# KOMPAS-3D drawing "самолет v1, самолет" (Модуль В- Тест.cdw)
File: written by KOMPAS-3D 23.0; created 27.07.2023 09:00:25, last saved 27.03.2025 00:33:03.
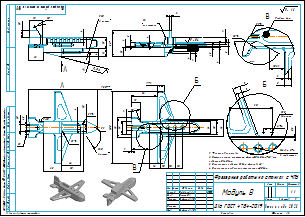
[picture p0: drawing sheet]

Sheet 1: A3, landscape

Document properties: Полное имя файла: C:\Users\safro\OneDrive\Рабочий стол\ИГ 2025\КЗ\Модуль В\Модуль В- Тест.cdw; Автор: Пользователь Windows

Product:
- Part/product: самолет v1  | designation самолет
    Масса: 0.217105
    source file: самолет.cdw

Title block, sheet 1: Наименование: Модуль В; designation: Фрезерные работы на станках с ЧПУ; Материал: Д16 ГОСТ 4784-2019; Количество листов документа: 1; organisation: Итоги года 2025; Форматы листов документа: A3; stored path: C:\Users\User\YandexDisk\Mastercam files\Чертежи\самолет\самолет.cdw; Разработал: Пивоваров А.А.; Проверил: Бажин Е.в.; Т. контр.: Сафронов А.Н.; Утвердил: Сафронов А.Н.; Разработал, date: 270723

Views: Вид 1, Сверху, Проекционный вид 3, Проекционный вид 4, Местный разрез 1, Местный разрез 2, Вид по стрелке 5, Выносной элемент 6, Выносной элемент 7, Вид по стрелке А, Выносной элемент Б, Выносной элемент, Выносной элемент В
Referenced files in C:\Users\safro\OneDrive\Рабочий стол\ИГ 2025\КЗ\Модуль В\: изометрия.png, обратная изометрия.png, самолет.m3d
Referenced files in C:\Users\User\YandexDisk\Mastercam files\Чертежи\самолет\: самолет.m3d
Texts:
  изометрия.png
  обратная изометрия.png
  1. *Размеры для справок
  2. Острые кромки притупить фаской 0,1-0,3мм*45° или
  радиусом 0,1-0,3мм
  3. Неуказанные радиусы R3.5мм, фаски 1х45°
  4. Неуказанные предельные отклонения ±0,05мм
  cil0_24705-2004 coarse.xml
  Метрическая резьба с крупным шагом ГОСТ 24705-2004
  Наружная резьба
  самолет
  Ra0.8
  Ra0.4
  Ra 1,6
  по контуру
  Ra1.0
  Глубина 6мм
  Основные
  Основные размеры
  Второстепенные
  Второстепенные Размеры
  Шерховатости
  Второстепенные размеры
  Стили документа
  самолет v1
  самолет самолет v1
Dimensions and other numbers on the sheet: 100; 20; 16; 24; 28; 7; 13; 36; 9,71; 1; 10; 18; 21; 6; 15; 30; 2 места; 11; 5; 9; 4; 1,5; 3; 2; 6,5; 25; 95,07; 26; 3,5; 16 мест; 0,5; 3 отверстия; 150; 10,21; 8; 12; 1:1; 270723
